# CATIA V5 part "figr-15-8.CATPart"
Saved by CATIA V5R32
Part number: Part1
Bounding box of the stored display mesh (mm): x -50 to 50, y -32.5 to 33.5, z -52 to 1
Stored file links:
  D:\PROJECTS\Project 2022\CATIA V5 6R 2022\Resources\Part Files\c15_catia_v5_6r2022_prt\figr-15-8.CATPart
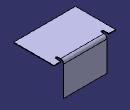
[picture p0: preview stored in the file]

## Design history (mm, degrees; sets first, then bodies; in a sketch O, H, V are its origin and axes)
SheetMetalParameters1: Thickness 1, BendRadius 4, KFactor 0.475772 {= log(min(100,max(20*SheetMetalParameters1.BendRadius,SheetMetalParameters1.Thickness)/SheetMetalParameters1.Thickness))/log(100)/2}, ReliefRadialLength 4, ReliefAxialLength 4, MinimumBendRadius 0
Body1 (main body)
  Sketch1 on xy-plane, origin (0, 0, 0), H (1, 0, 0), V (0, 1, 0)
    line L1 (-50, 32.5) -> (50, 32.5)
    line L2 (50, 32.5) -> (50, -32.5)
    line L3 (50, -32.5) -> (-50, -32.5)
    line L4 (-50, -32.5) -> (-50, 32.5)
    length L1 = 100
    length L2 = 65
    horizontal: L1 H, L3 H
    vertical: L2 V, L4 V
    symmetry: L4 L2 V, L1 L3 H
  Wall1: Thickness 1, Profile Sketch1
  d_NewWallOnEdge1: NewWallOnEdge_Edge edge [face of Wall1 | face of Wall1], NewWallOnEdge_Length 53, NewWallOnEdge_HeightLimitOffset 0, NewWallOnEdge_WidthOffset1 -15, NewWallOnEdge_WidthOffset2 -15, NewWallOnEdge_Angle 90, NewWallOnEdge_BendRadiusValue 4 {= SheetMetalParameters1.BendRadius}, NewWallOnEdge_BendTable SheetMetalParameters1, KFacteur 0.475772 {= log(min(100,max(20*d_NewWallOnEdge1.Radius,SheetMetalParameters1.Thickness)/SheetMetalParameters1.Thickness))/log(100)/2}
